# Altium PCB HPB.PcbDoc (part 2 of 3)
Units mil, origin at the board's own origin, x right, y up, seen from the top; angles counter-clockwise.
Board outline 7000 x 12000 mil, 6 copper layers (Top Layer, Int1 (GND), Int2 (Sign), Int3 (Sign), Int4 (PWR), Bottom Layer), stack 61.068 mil thick; 321 components, 232 nets, 1034 pads, 269 vias.
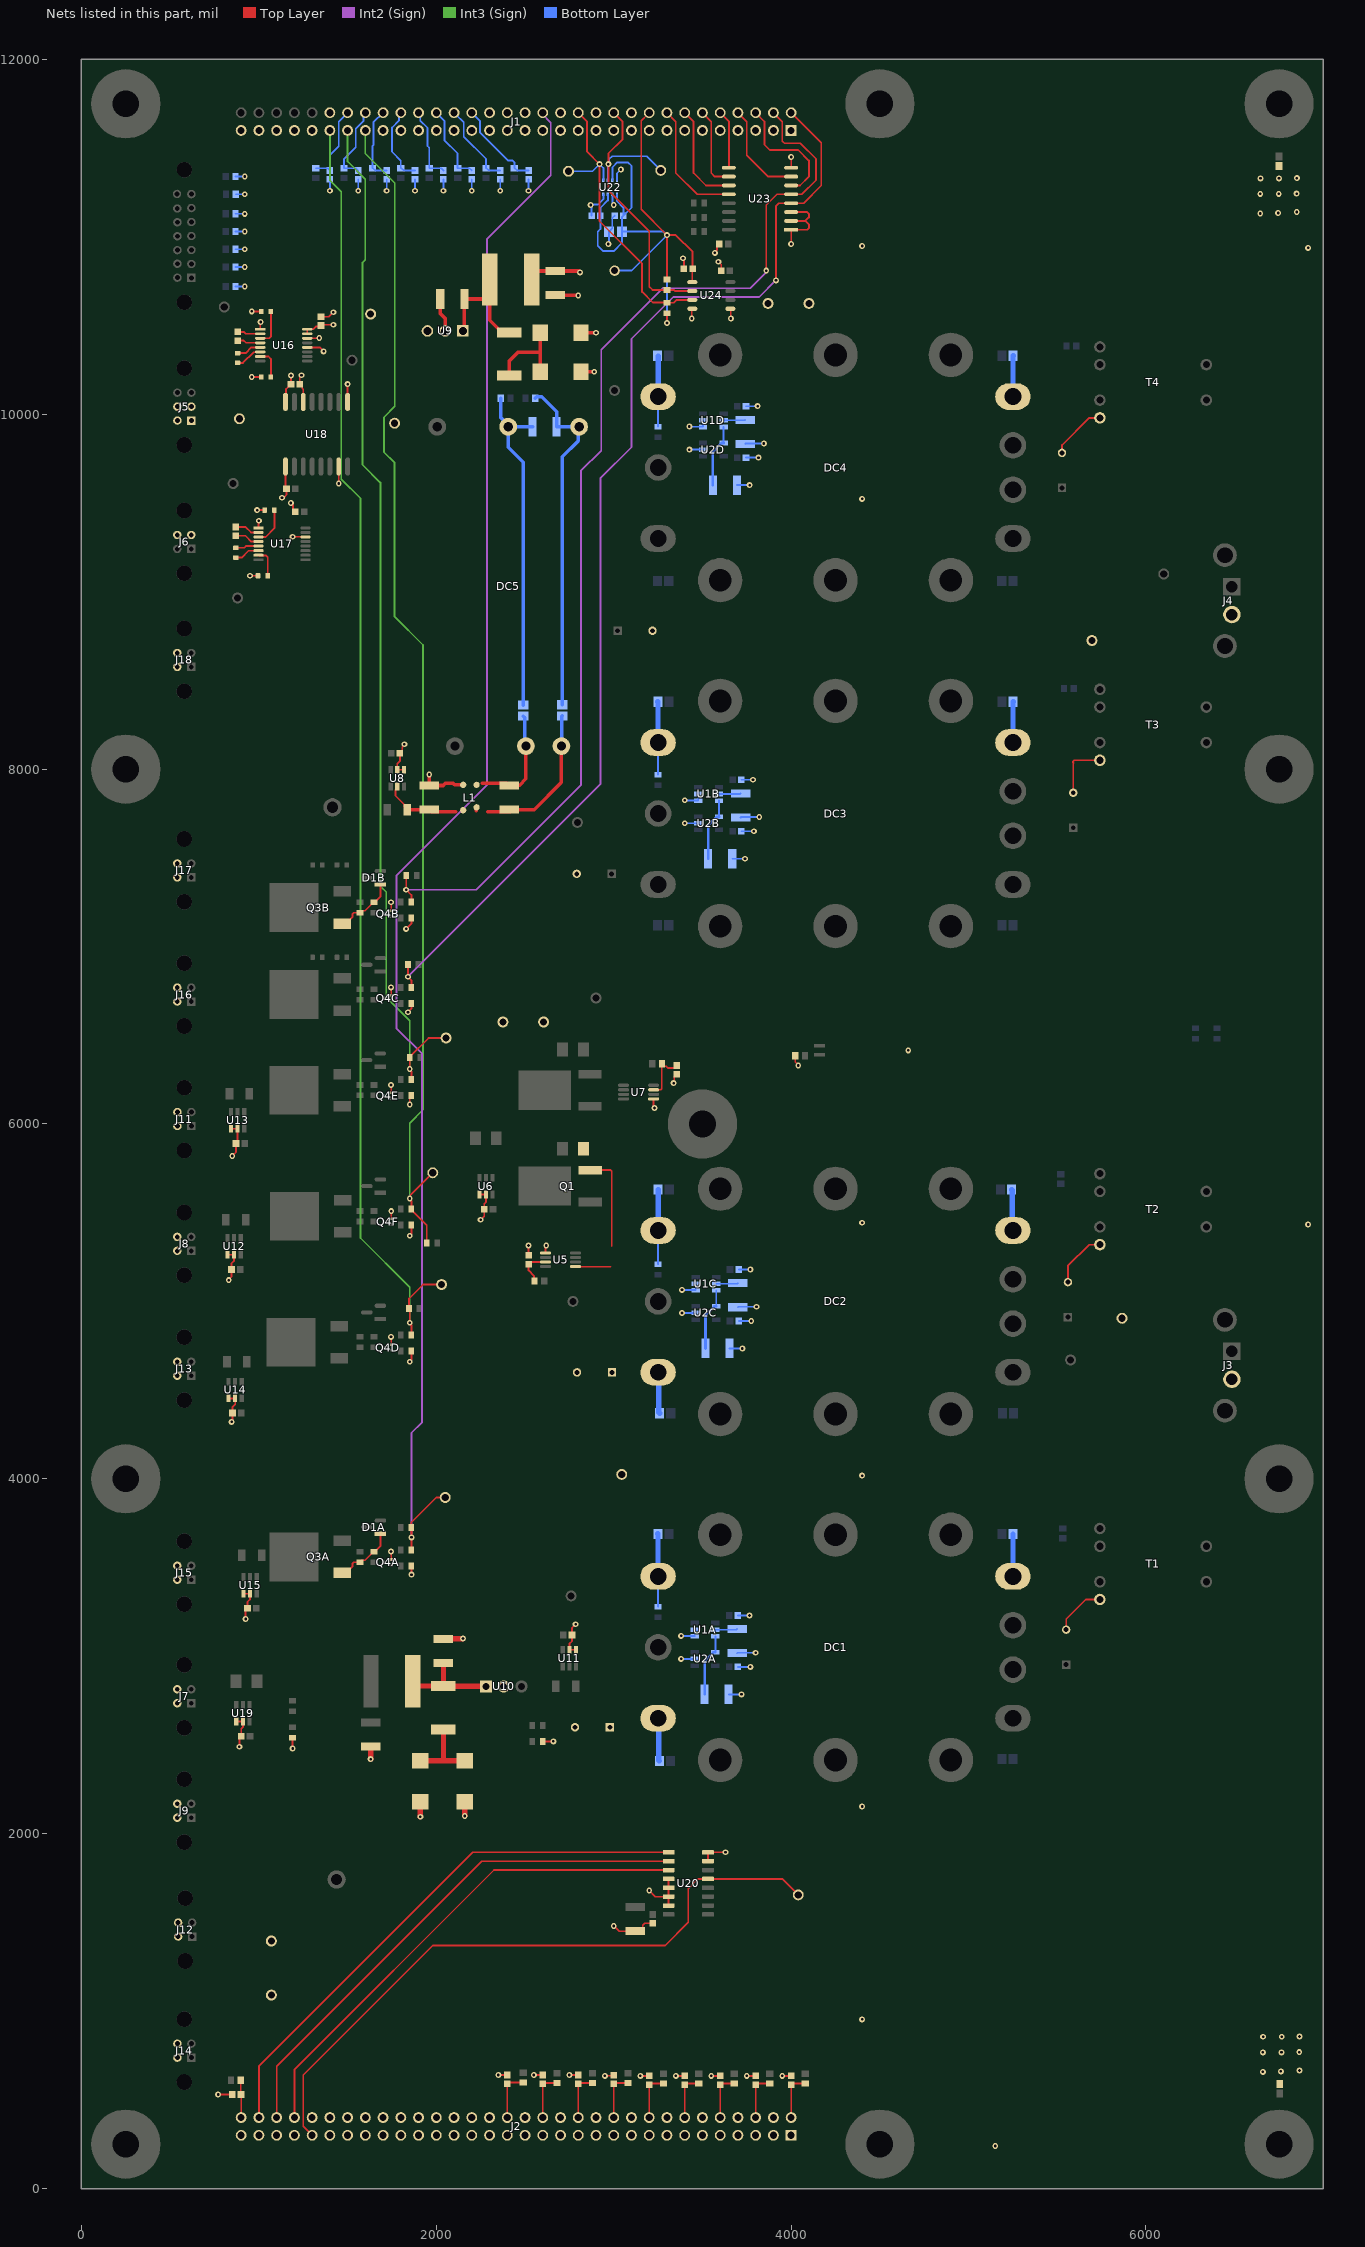
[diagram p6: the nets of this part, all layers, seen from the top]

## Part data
C1 C2 C5 C6 C7 C8 C16 C17 C18 C19 C22 C23 C26 C27 C30 C31 C32 C36: library part CMP-001-00109-9, "0805 Arcshield HV 4.7nF Ceramic Multilayer Cap; 1000VDC; +125C; X7R Dielec; +/-10%", Capacitance=4.7nF, Case Code (Imperial)=0805, Dielectric=X7R, Dielectric Material=Ceramic, Max Operating Temperature=125°C, Min Operating Temperature=-55°C, Tolerance=10%, Voltage Rating=1kV
C3 C4 C14 C15 C20 C21 C28 C29: library part CMP-001-00084-11, "Cap Ceramic 0.22uF 1000V X7R 20% Radial 5mm 125°C Bulk", Capacitance=220nF, Case/Package=Radial, Dielectric=X7R, Manufacturer PN=RDER73A224MUB1H03B, Max Operating Temperature=125°C, Min Operating Temperature=-55°C, Resistor Type=Ceramic, Tolerance=20%, Voltage=1kV
C13 C24 C25 C37 C38 C45 C46 C49 C50 C51 C52 C53 C54 C55 C56 C57 C58 C65 C66 C67 C68 C69 C70 C72 C73 C74 C75 C76 C77 C78 C79 C80 C82 C83 C84 C85 C86 C87 C88 C89 C90A C90B C90C C90D C93A C93B C93C C93D: library part CMP-001-00017-14, "Chip Capacitor, 100 nF, +/- 10%, 50 V, 0603 (1608 Metric)", Capacitance=100nF, Capacitor Type=Ceramic, Case/Package=0603, Max Operating Temperature=125°C, Min Operating Temperature=-55°C, Tolerance=10%, Voltage Rating=50V
C33 C34 C35 C39 C43: library part CMP-001-00184-9, "Chip Capacitor, 10uF, 10%, 50 V, X7R 1210 (3225 Metric)", Capacitance=10uF, Capacitor Type=Ceramic, Case/Package=1210, Dielectric=X7R, Max Operating Temperature=125°C, Min Operating Temperature=-55°C, Tolerance=10%, Voltage Rating=50V
C40 C44: library part CMP-001-00183-9, "Chip Capacitor, 4.7uF, 10%, 50 V, X7R 1210 (3225 Metric)", Capacitance=4.7uF, Capacitor Type=Ceramic, Case/Package=1210, Dielectric=X7R, Max Operating Temperature=125°C, Min Operating Temperature=-55°C, Tolerance=10%, Voltage Rating=50V
C41 C42 C47 C48: library part CMP-001-00088-9, "10uF Solid MnO2 Tantalum Electrolytic Capacitor; 50 V dc +/-10%; T491 Series", Capacitance=10uF, Case Code (Imperial)=2917, Dielectric Material=Tantalum, ESR (Equivalent Series Resistance)=800mR, Leakage Current=5uA, Manufacturer=KEMET, Max Operating Temperature=125°C, Min Operating Temperature=-55°C, Package Quantity=20, Ripple Current=433mA, Tolerance=10%, Voltage=50V
C59 C60 C61 C62 C63 C64: library part CMP-001-00077-11, "Chip Capacitor, 470nF +/-20%, 25V, 0603, Thickness 1 mm", Capacitance=470nF, Capacitor Type=Ceramic, Case/Package=0603, Max Operating Temperature=85°C, Min Operating Temperature=-55°C, Tolerance=10%, Voltage Rating=25V
C71 C91A C91B C91C C91D C92A C92B C92C C92D: library part CMP-001-00181-9, "Chip Capacitor, 1uF, 10%, 50 V, X7R 1210 (3225 Metric)", Capacitance=1uF, Capacitor Type=Ceramic, Case/Package=1210, Dielectric=X7R, Max Operating Temperature=125°C, Min Operating Temperature=-55°C, Tolerance=10%, Voltage Rating=50V
C81: library part CMP-001-00167-10, "Chip Capacitor, 2.2uF, 10%, 50 V, X7R 0805 (2012 Metric)", Capacitance=2.2uF, Capacitor Type=Ceramic, Case/Package=0805, Dielectric=X7R, Max Operating Temperature=125°C, Min Operating Temperature=-55°C, Tolerance=10%, Voltage Rating=50V
D1A D1B D1C D1D D1E D1F: library part CMP-004-00069-1, "Diode Zener Single 10 Volt 5% 250m Watt Automotive 3-Pin SOT-23"
DC1 DC2 DC3 DC4: library part CMP-019-00060-1, "375C Series 150 W Single Output 24 V DC-DC Converter", Isolation Voltage=3kV, Max Input Voltage=425V, Max Operating Temperature=100°C, Max Output Current=6.25A, Max Power Dissipation=150W, Min Input Voltage=250V, Min Operating Temperature=-20°C, Output Voltage=24V
DC5: library part CMP-019-00061-2, "30W DC/DC-Converter 'MEDLINE' 2\"x1\" 5kV reg 4: 1", Current - Output (Max)=1.25A, Operating Temperature="-40°C ~ 105°C (With Derating)", Package / Case="6-DIP Module, 5 Leads", Power (Watts)="30 W", Voltage - Input (Max)=36V, Voltage - Input (Min)=9V, Voltage - Isolation="5 kV", Voltage - Output 1=24V
FB1 FB2: library part CMP-00000-1, "Ferrite Beads Multi-Layer 120Ohm 25% 100MHz 3A 0.025Ohm DCR 0603 T/R", Case Code (Imperial)=0603, Case Code (Metric)=1608, Current Rating=3A, DC Resistance (DCR)=25mR, Frequency=100MHz, Max Operating Temperature=125°C, Min Operating Temperature=-55°C, Package Quantity=1, Tolerance=25%
J1 J2: library part CMP-002-00093-2, "Conn Elevated Socket SKT 64 POS 2.54mm Solder ST Top Entry Thru-Hole Tube", Color=Black, Contact Resistance=10mR, Current Rating=6.9A, Max Operating Temperature=125°C, Max Voltage Rating (AC)=550V, Min Operating Temperature=-55°C, Package Quantity=1
J3 J4: library part CMP-002-00075-3, "Conn Header R/a 2POS 4MM", Color=Black, Contact Resistance=25mR, Current Rating=40A, Insulation Resistance=100MR, Manufacturer=Harwin, Max Operating Temperature=125°C, Maximum Voltage=800V, Min Operating Temperature=-55°C
J5: library part CMP-002-00076-5, "Conn Header R/a 6POS 2MM", Color=Black, Contact Resistance=25mR, Current Rating=3A, Insulation Resistance=100MR, Manufacturer=Harwin, Max Operating Temperature=125°C, Max Voltage Rating (AC)=120V, Maximum Voltage=800V, Min Operating Temperature=-55°C
J6 J7 J8 J9 J11 J12 J13 J14 J15 J16 J17 J18: library part CMP-002-00095-3, "HARWIN - M80-5400442 - Wire-To-Board Connector, 2 mm, 4 Contacts, Header, Datamate J-Tek M80 Series, Through Hole, 2 Rows", Color=Black, Contact Resistance=25mR, Current Rating=2.2A, Insulation Resistance=100MR, Manufacturer=Harwin, Max Operating Temperature=125°C, Maximum Voltage=800V, Min Operating Temperature=-55°C
J10: library part CMP-002-00100-2, "Conn Datamate M 14 POS 2mm Solder RA Thru-Hole Tube", Color=Black, Contact Resistance=25mR, Current Rating=3A, Manufacturer=Harwin, Max Operating Temperature=125°C, Min Operating Temperature=-55°C, Voltage Rating=800V
J19 J20 J21 J22 J23 J24 J25 J26 J27 J28 J29 J30 J31 J32 J33 J34 J35 J36 J37 J38 J39 J40 J41 J42: library part CMP-002-00083-3, "TEST POINT PC MINI .040D WHITE", Color=White
L1: library part CMP-006-00027-1, "Ind Common Mode Choke Wirewound 100 Ohm 100MHz 6A 2020 Embossed T/R", Case/Package=2020, DC Resistance (DCR)=13mR, Max Current Rating=6A, Max Operating Temperature=85°C, Min Operating Temperature=-40°C, Resistor Type=Wirewound, Test Frequency=100MHz, Tolerance=40%, Voltage Rating (DC)=50V
L2 L3: library part CMP-006-00026-2, "WE-LQS Series; Shielded Wire-wound SMD Inductor 12", Case/Package=Nonstandard, Current Rating=2.8A, DC Resistance (DCR)=40mR, Inductance=12uH, Inductance Tolerance=20%, Max Operating Temperature=125°C, Min Operating Temperature=-40°C, Resistor Type=Wirewound, Saturation Current=3.8A, Self Resonant Frequency=21MHz, Test Frequency=100kHz
MH1 MH2 MH3 MH4 MH5 MH6 MH7 MH8 MH9 MH10 MH11: library part CMP-00028-00015-1, "MARS2 Project 6-32 Mounting Hole Plated ."
Q1 Q2: library part CMP-013-00055-1, "Trans MOSFET N-CH 100V 70A Automotive 3-Pin(2+Tab) DPAK T/R", Case/Package=TO-252-3, Continuous Drain Current (ID)=70A, Drain to Source Voltage (Vdss)=100V, Input Capacitance=3.1nF, Max Operating Temperature=175°C, Max Power Dissipation=85W, Min Operating Temperature=-55°C
Q3A Q3B Q3C Q3D Q3E Q3F: library part CMP-013-00042-2, "MOSFET P-CH 100V 13A DPAK", Case/Package=TO-252-3, Continuous Drain Current (ID)=13A, Drain to Source Breakdown Voltage=-100V, Drain to Source Resistance=205mR, Gate to Source Voltage (Vgs)=20V, Input Capacitance=760pF, Max Operating Temperature=150°C, Max Power Dissipation=66W, Min Operating Temperature=-55°C, Threshold Voltage=-4V
Q4A Q4B Q4C Q4D Q4E Q4F: library part CMP-013-00028-3, "NPN General Purpose Transistor, 3-Pin SOT-723, Pb-Free, Tape and Reel", Case/Package=SOT-723
R1 R6 R14 R17: library part CMP-009-01151-1, "Chip Resistor, 75 Ohm, +/- 1%, 0.1 W, -55 to 155 degC, 0603 (1608 Metric)", Case/Package=0603, Max Operating Temperature=155°C, Min Operating Temperature=-55°C, Power=100mW, Tolerance=1%, Voltage Rating=75V
R11 R16 R21 R25: library part CMP-009-01001-3, "Chip Resistor, 49.9k Ohm, +/- 1%, 0.1 W, -55 to 155 degC, 0603 (1608 Metric)", Case/Package=0603, Max Operating Temperature=155°C, Min Operating Temperature=-55°C, Power=100mW, Tolerance=1%, Voltage Rating=75V
R12 R13: library part CMP-009-00006-6, "Chip Resistor, 0 Ohm, 0.1 W, -55 to 155 degC, 0603 (1608 Metric)", Case/Package=0603, Max Operating Temperature=155°C, Min Operating Temperature=-55°C, Power=100mW, Tolerance=5%, Voltage Rating=50V
R15 R18 R19 R49: library part CMP-009-01193-1, "Res Metal Strip 1206 0.01 Ohm 1% 1W ±75ppm/°C Molded SMD SMD Embossed Plastic T/R", Case Code (Imperial)=1206, Manufacturer PN=WSLP1206R0100FEA, Max Operating Temperature=170°C, Max Power Dissipation=1W, Min Operating Temperature=-65°C, Resistance=10mR, Resistance Tolerance=1%, Resistor Type="Metal Strip", Temperature Coefficient=75ppm/°C
R20: library part CMP-009-01006-3, "Chip Resistor, 56.2k Ohm, +/- 1%, 0.1 W, -55 to 155 degC, 0603 (1608 Metric)", Case/Package=0603, Max Operating Temperature=155°C, Min Operating Temperature=-55°C, Power=100mW, Tolerance=1%, Voltage Rating=75V
R22 R23 R28 R34 R35 R38 R40 R42 R46 R50 R51 R52 R53 R54 R55 R61 R62 R63: library part CMP-009-01135-1, "Chip Resistor, 51.1 Ohm, +/- 1%, 0.1 W, -55 to 155 degC, 0603 (1608 Metric)", Case/Package=0603, Max Operating Temperature=155°C, Min Operating Temperature=-55°C, Power=100mW, Tolerance=1%, Voltage Rating=75V
R24 R33 R70A R70B R70C R70D R70E R70F R71A R71B R71C R71D R71E R71F R77A R77B R77C R77D R77E R77F R78A R78B R78C R78D R78E R78F: library part CMP-009-00017-7, "Chip Resistor, 10 KOhm, +/- 1%, 01 W, -55 to 155 degC, 0603 (1608 Metric)", Case/Package=0603, Max Operating Temperature=155°C, Min Operating Temperature=-55°C, Power=100mW, Tolerance=1%, Voltage Rating=50V
R26 R31 R37 R39 R41 R45: library part CMP-009-01194-1, "Res Thick Film 1206 0.033 Ohm 1% 1W ±75ppm/C Pad SMD Automotive T/R", Case Code (Imperial)=1206, Manufacturer PN=ERJ-8CWFR033V, Max Operating Temperature=125°C, Max Power Dissipation=1W, Min Operating Temperature=-55°C, Ratings=AEC-Q200, Resistance=33mR, Resistance Tolerance=1%, Temperature Coefficient=75ppm/°C
R27: library part CMP-009-01065-1, "Chip Resistor, 100k Ohm, +/- 1%, 0.1 W, -55 to 155 degC, 0603 (1608 Metric)", Case/Package=0603, Max Operating Temperature=155°C, Min Operating Temperature=-55°C, Power=100mW, Tolerance=1%, Voltage Rating=75V
R29: library part CMP-009-01062-1, "Chip Resistor, 931k Ohm, +/- 1%, 0.1 W, -55 to 155 degC, 0603 (1608 Metric)", Case/Package=0603, Max Operating Temperature=155°C, Min Operating Temperature=-55°C, Power=100mW, Tolerance=1%, Voltage Rating=75V
R30 R32: library part CMP-009-01195-2, "Res Thick Film 2512 1 Ohm 1% 1W ±100ppm/°C Molded SMD SMD", Case Code (Imperial)=2512, Manufacture PN=CRCW25121R00FKEG, Max Operating Temperature=155°C, Max Power Dissipation=1W, Min Operating Temperature=-55°C, Ratings=AEC-Q200, Resistance=1R, Resistance Tolerance=1%, Resistor Type="Thick Film", Temperature Coefficient=100ppm/°C, Voltage Rating=500V
R36 R69A R69B R69C R69D R69E R69F: library part CMP-009-00023-6, "Chip Resistor, 100 KOhm, +/- 1%, 0.1 W, -55 to 155 degC, 0603 (1608 Metric)", Case/Package=0603, Max Operating Temperature=155°C, Min Operating Temperature=-55°C, Power=100mW, Tolerance=1%, Voltage Rating=50V
R43 R44 R47 R48: library part CMP-009-00175-3, Case/Package=0603, Max Operating Temperature=155°C, Min Operating Temperature=-55°C
R56 R57 R58 R59 R60 R64 R65 R66: library part CMP-009-00865-4, "Chip Resistor, 7.15k Ohm, +/- 1%, 0.1 W, -55 to 155 degC, 0603 (1608 Metric)", Case/Package=0603, Max Operating Temperature=155°C, Min Operating Temperature=-55°C, Power=100mW, Tolerance=1%, Voltage Rating=75V
R67 R68 R72 R73 R74: library part CMP-009-00031-7, "Chip Resistor, 4.7 KOhm, +/- 1%, 0.1 W, -55 to 155 degC, 0603 (1608 Metric)", Case/Package=0603, Max Operating Temperature=155°C, Min Operating Temperature=-55°C, Power=100mW, Tolerance=1%
R75 R76: library part CMP-009-01066-2, "Chip Resistor, 100 Ohm, +/- 1%, 0.1 W, -55 to 155 degC, 0603 (1608 Metric)", Case/Package=0603, Max Operating Temperature=155°C, Min Operating Temperature=-55°C, Power=100mW, Tolerance=1%, Voltage Rating=75V
SY: library part CMP-00028-00011-3, "Layer Indicator for 6 layer board"
T1 T2 T3 T4: library part CMP-012-00000-1, "3 W 101 to 187 uH 40 to 50 mOhm DCR PR Bus Toroidal Inductor", Manufacturer=Vicor
TP1 TP2: library part CMP-001-0000-5, "PC TEST POINT COMPACT RED", Color=Red
TP3: library part CMP-002-00037-2, "Test Point, Orange, Height 4.6 mm, Tail Length 3 mm, 1-Pin THD, RoHS", Colour=Orange, Manufacturer=Keystone, Package Description="1-Pin Through Hole Device, Dia 2.54 mm", Package Quantity=10
TP4 TP5 TP6 TP7 TP8 TP9: library part CMP-001-0002-3, "TEST POINT PC MINI .040D BLACK", Color=Black
U1A U1B U1C U1D: library part CMP-019-00086-3, "650-nA quiescent current, 12-ppm/°C drift, ultra-low-power precision voltage reference, 1.024V, 6-SOT-23 -40 to 125"
U2A U2B U2C U2D: library part CMP-014-00029-3, "Automotive, 2.5-ns, high-speed, rail-to-rail comparator with push-pull outputs 5-SOT-23 -40 to 125"
U5 U7: library part CMP-004-00036-2, "OR Controller N+1 ORing Controller N-Channel N:1 8-MSOP", Case/Package=MSOP, Max Operating Temperature=125°C, Max Output Current=210uA, Max Supply Voltage=80V, Min Operating Temperature=-40°C, Min Supply Voltage=9V
U6 U19: library part CMP-014-00007-3, "MAX4173 Series 28 V 1.4 MHz Voltage Current Sense Operational Amplifier - SOT-23", Input Bias Current=700uA, Input Offset Voltage (Vos)=300uV, Max Operating Temperature=85°C, Max Supply Current=1mA, Max Supply Voltage=28V, Min Operating Temperature=-40°C, Min Supply Voltage=3V, Nominal Supply Current=420uA
U8 U11 U12 U13 U14 U15: library part CMP-014-00008-1, "MAX4173 Series 28 V 1.2 MHz Voltage Current Sense Operational Amplifier - SOT-23", Input Bias Current=700uA, Max Operating Temperature=85°C, Max Supply Voltage=28V, Min Operating Temperature=-40°C, Min Supply Voltage=3V, Operating Supply Current=420uA
U9: library part CMP-019-00059-1, "0.5A DC/DC-Converter 'INNOLINE' SIP3 reg; V. In: 7-28; V. Out: 5.0; mA. Out: 500", Case/Package=SIP, Current - Output 1=500mA, Max Input Voltage=28V, Max Operating Temperature=85°C, Max Output Power=2.5W, Max Output Voltage=5V, Max Power Dissipation=3W, Min Input Voltage=7V, Min Operating Temperature=-40°C
U10: library part CMP-019-00062-2, "0.5A DC/DC-Converter 'INNOLINE' SIP3 reg; V. In: 6.5-32; V. Out: 5.0; mA. Out: 500", Case/Package=SIP, Current - Output 1=500mA, Isolation Voltage=2kV, Max Input Voltage=32V, Max Operating Temperature=85°C, Max Output Power=2.5W, Max Output Voltage=5V, Max Power Dissipation=3W, Min Input Voltage=6.5V, Min Operating Temperature=-40°C, Nominal Input Voltage=24V, Switching Frequency=380kHz
U16 U17: library part CMP-015-00011-1, "MAX3221 Series 235 kbps 5.5 V Surface Mount RS-232 Transceiver - SSOP-16"
U18: library part CMP-015-00014-3, "5000Vrms 25kV/us 1Mbps Digital Isolation RS232,TTL RS485", Case/Package=SOIC, Isolated Power=No, Max Input Current=10uA, Max Operating Temperature=105°C, Max Supply Voltage=5.5V, Min Operating Temperature=-40°C, Min Supply Voltage=3V, Nominal Supply Current=800uA
U20: library part CMP-016-00018-2, "Automotive 5-V, 8: 1 1-channel general-purpose multiplexer 16-SOIC -40 to 125", Case/Package=SOIC, High Level Output Current=7.8mA, Max Operating Temperature=125°C, Max Supply Voltage=6V, Min Operating Temperature=-40°C, Min Supply Voltage=2V
U21: library part CMP-010-00024-2, "SENSOR ANALOG -55C-150C 2FLATPK / Two-Twrminal IC Temperature Transducer", Case/Package=Ceramic, Forward Voltage=44V, Max Operating Temperature=150°C, Max Supply Voltage=30V, Min Operating Temperature=-55°C, Min Supply Voltage=4V, Output Current=298.2uA
U22: library part CMP-010-00027-1, "SENSOR PRESSURE HUMIDITY TEMP", Max Operating Temperature=85°C, Min Operating Temperature=-40°C
U23: library part CMP-015-00015-1, "8-bit 1.65- to 5.5-V I2C/SMBus I/O expander with interrupt, & config registers 16-SOIC -40 to 85", Case/Package=SOIC, Frequency=400kHz, Max Operating Temperature=85°C, Min Operating Temperature=-40°C
U24: library part CMP-024-00005-1, "I²C Digital Isolator 2500Vrms 2 Channel 1Mbps 25kV/µs CMTI 8-SOIC (0.154, 3.90mm Width)", Max Operating Temperature=105°C, Max Supply Voltage=5.5V, Min Operating Temperature=-40°C, Min Supply Voltage=3V, Nominal Supply Current=5mA, Operating Supply Voltage=5V

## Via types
v1: diameter 33, hole 15, Top Layer to Bottom Layer, 269 vias

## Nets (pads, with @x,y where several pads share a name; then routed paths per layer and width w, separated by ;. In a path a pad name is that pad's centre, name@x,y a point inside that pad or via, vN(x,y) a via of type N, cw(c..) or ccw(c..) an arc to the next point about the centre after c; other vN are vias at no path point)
24V_UNSWCH_BUS_CURRENT: C69.2 J2.18 R50.2 | length 268.3
  Top Layer w10: J2.18@3200,400 C69.2@3200,585.39 3207.05,592.44 R50.2@3280,592.44
BAYCAT_3V3: C81.2 C82.2 C83.2 C84.2 J1.18 R67.2 R68.2 TP3.1 U22.2 U22.6 U22.8 U24.1 | length 3841.2
  Top Layer w10: J1.18@3200,11700 3200,11690 3190,11690 3154.49,11654.49 3154.49,11155.51 v1(3300,11010) ; v1(3300,10515) R67.2@3300,10570.47 ; R68.2@3300,10760 v1(3300,11010) ; U24.1@3442.72,10745 3442.72,10818.11 C84.2@3444.61,10820 3444.61,10915.39 3350,11010 v1(3300,11010)
  Bottom Layer w10: U22.6@2967.2,11239.65 2967.2,11205.55 2924.61,11162.95 C82.2@2924.61,11120 2924.61,11044.61 2910,11030 2910,10950 2940,10920 3000,10920 3046.42,10966.42 C81.2@3046.42,11030 ; U22.2@2992.8,11320.35 2992.8,11392.8 3020,11420 3080,11420 3100,11400 3100,11165.39 C83.2@3054.61,11120 ; TP3.1@3005,10810 3100,10810 v1(3300,11010) ; U22.8@3018.39,11239.65 3018.39,11201.61 3054.61,11165.39 C83.2@3054.61,11120 ; v1(3300,10515) v1(3300,11010) ; C81.2@3046.42,11030 3280,11030 v1(3300,11010) ; C81.2@3046.42,11030 3046.42,11111.81 C83.2@3054.61,11120
CHASIS1: FB1.1
  other v1: 4400,9523.34 6914.03,10938.34 4400,10948.34 6643.58,11132.33 6745,11135 6850,11140 6643.58,11242.33 6748.58,11242.33 6848.9,11243.8 6645,11330 6750,11330 6850.32,11331.47
CHASIS2: FB2.1
  other v1: 5150,240 6658.58,657.33 6760,660 6865,665 6658.58,767.33 6763.58,767.33 6863.9,768.8 6660,855 6765,855 6865.32,856.47 4400,953.34 4400,2153.34 4400,4018.34 6914.03,5433.34 4400,5443.34 4660,6415
DIO_SPARE_0: J1.2 R70C.1 R77C.1 U23.4 | length 6409.9
  Top Layer w10: R77C.1@1840.47,6900 1840,6899.53 v1(1840,6830) 1859.53,6810.47 R70C.1@1859.53,6770 ; v1(3915,10755) 3915,11175 3930,11190 U23.4@4000,11190 4070,11190 4170,11290 4170,11530 J1.2@4000,11700
  Int2 (Sign) w10: v1(1840,6830) 2925,7915 2925,9640 3100,9815 3100,10425 3336.11,10661.11 3819.56,10661.11 3913.45,10755 v1(3915,10755)
DIO_SPARE_1: J1.4 R70B.1 R77B.1 U23.5 | length 6258.4
  Top Layer w10: R77B.1@1830.94,7400 1830,7399.06 v1(1830,7320) 1859.53,7290.47 R70B.1@1859.53,7250 ; v1(3860,10810) 3860,11180 3920,11240 U23.5@4000,11240 4060,11240 4140,11320 4140,11440 4052.18,11527.82 3962.18,11527.82 3950,11540 3950,11650 J1.4@3900,11700
  Int2 (Sign) w10: v1(1830,7320) 2225,7320 2815,7910 2815,9680 2814.14,9680.86 2929.09,9795.81 2929.09,10364.09 3278.36,10713.36 3286.64,10713.36 3290,10710 3770,10710 3857.13,10797.13 3857.13,10807.13 v1(3860,10810)
DIO_SPARE_2: J1.6 U23.6 | length 698.7
  Top Layer w10: J1.6@3800,11700 3850,11650 3850,11520 3880,11490 4040,11490 4100,11430 4100,11340 4050,11290 U23.6@4000,11290
DIO_SPARE_3: J1.8 U23.7 | length 560.4
  Top Layer w10: J1.8@3700,11700 3750,11650 3750,11460 3870,11340 U23.7@4000,11340
DIO_SPARE_4: J1.10 U23.9 | length 331.4
  Top Layer w10: J1.10@3600,11700 3650,11650 3650,11391.61 U23.9@3648.39,11390
DIO_SPARE_5: J1.12 U23.10 | length 467.4
  Top Layer w10: J1.12@3500,11700 3550,11650 3550,11360 3570,11340 U23.10@3648.39,11340
DIO_SPARE_6: J1.14 U23.11 | length 588.1
  Top Layer w10: J1.14@3400,11700 3450,11650 3450,11360 3520,11290 U23.11@3648.39,11290
DIO_SPARE_7: J1.16 U23.12 | length 708.8
  Top Layer w10: J1.16@3300,11700 3350,11650 3350,11360 3470,11240 U23.12@3648.39,11240
FAULT_MUX_A: J2.58 U20.11 | length 2844.8
  Top Layer w10: J2.58@1200,400 1200,670 2325,1795 U20.11@3308.78,1795
FAULT_MUX_B: J2.60 U20.10 | length 2977.2
  Top Layer w10: J2.60@1100,400 1100,690 2255,1845 U20.10@3308.78,1845
FAULT_MUX_C: J2.62 U20.9 | length 3097.9
  Top Layer w10: J2.62@1000,400 1000,690 2205,1895 U20.9@3308.78,1895
FAULT_SENSE_HCB: J2.55 J40.1 U20.5 | length 3757
  Top Layer w10: J2.55@1300,300 1250,350 1250,640 1980,1370 3290,1370 3420,1500 3420,1690 3475,1745 3950,1745 J40.1@4040,1655
FAULT_SENSE_IPB1: J2.51
FAULT_SENSE_IPB2: J2.53
GF_AMP_TEMP_F: J2.59
GF_ANNODE_SEL_EN: J2.9
GF_CHASSIS_SEL_EN: J2.11
GF_SIG: J2.47
GF_SOURCE_SEL_A: J2.1
GF_SOURCE_SEL_B: J2.3
GF_SOURCE_SEL_C: J2.5
GF_SOURCE_SEL_ENn: J2.7
GNDA: C4.2 C6.2 C13.1 C15.2 C17.2 C21.2 C23.2 C24.1 C25.1 C29.2 C31.2 C34.1 C37.1 C38.1 C43.1 C44.1 C45.1 C46.1 C47.2 C48.2 C49.1 C50.1 C51.1 C52.1 C53.1 C54.1 C55.1 C56.1 C62.1 C63.1 C65.1 C66.1 C69.1 C70.1 C71.1 C72.1 C73.1 C74.1 C75.1 C76.1 C77.1 C78.1 C79.1 C80.1 C81.1 C82.1 C83.1 C84.1 C85.1 C86.1 C87.1 C88.1 C89.1 C90A.1 C90B.1 C90C.1 C90D.1 C91A.1 C91B.1 C91C.1 C91D.1 C92A.1 C92B.1 C92C.1 C92D.1 C93A.1 C93B.1 C93C.1 C93D.1 DC1.5 DC2.5 DC3.5 DC4.5 J1.20 J1.24 J1.28 J1.32 J1.54 J1.55 J1.57 J1.59 J1.61 J1.63 J2.4 J2.8 J2.12 J2.13 J2.16 J2.17 J2.20 J2.21 J2.24 J2.25 J2.28 J2.29 J2.32 J2.33 J2.37 J2.40 J2.41 J2.44 J2.45 J2.48 J2.49 J2.52 J2.56 J6.2 J6.4 J7.3 J7.4 J8.3 J8.4 J9.3 J9.4 J11.3 J11.4 J12.3 J12.4 J13.3 J13.4 J14.3 J14.4 J15.3 J15.4 J16.3 J16.4 J17.3 J17.4 J18.3 J18.4 L1.2 Q4A.2 Q4B.2 Q4C.2 Q4D.2 Q4E.2 Q4F.2 R11.2 R16.2 R21.2 R24.1 R25.2 R36.1 R56.1 R57.1 R58.1 R59.1 R60.1 R64.1 R65.1 R66.1 R71A.1 R71B.1 R71C.1 R71D.1 R71E.1 R71F.1 TP4.1 TP5.1 TP6.1 TP7.1 TP8.1 TP9.1 U1A.1 U1A.2 U1B.1 U1B.2 U1C.1 U1C.2 U1D.1 U1D.2 U2A.2 U2B.2 U2C.2 U2D.2 U5.5 U6.1 U6.2 U7.5 U8.1 U8.2 U10.2 U11.1 U11.2 U12.1 U12.2 U13.1 U13.2 U14.1 U14.2 U15.1 U15.2 U17.1 U17.14 U18.1 U18.7 U19.1 U19.2 U20.7 U20.8 U20.12 U20.13 U20.14 U20.15 U22.1 U22.5 U22.7 U23.1 U23.2 U23.3 U23.8 U24.4 U24.5 | length 10776.6
  Top Layer w10: v1(770,530) C56.1@850,530 ; U12.1@822.6,5262.76 U12.2@860,5262.76 860,5230 845.39,5215.39 C53.1@845.39,5180 845.39,5139.45 830,5124.06 v1(830,5120) ; U14.1@828.7,4453.58 U14.2@866.1,4453.58 866.1,4420.83 851.5,4406.22 C52.1@851.5,4370.83 851.5,4326.22 v1(846.1,4320.83) ; U13.1@842.6,5972.76 U13.2@880,5972.76 880,5899.21 C54.1@870.79,5890 870.79,5840.79 v1(850,5820) ; U19.1@872.6,2632.76 U19.2@910,2632.76 910,2600 900.79,2590.79 C70.1@900.79,2550 C70.1@890,2560.79 ; v1(890,2490) C70.1@890,2550 ; U15.1@919.41,3352.76 U15.2@950,3352.76 950,3320.46 935.39,3305.86 C87.1@935.39,3270 925,3259.61 v1(925,3210) ; v1(950,9090) C63.1@994.88,9090 ; v1(990,9460) C62.1@1032.44,9460 ; U17.1@997.57,9359.57 997.57,9397.57 v1(1000,9400) ; v1(1130,9530) 1132.87,9532.87 1141.96,9532.87 1155.39,9546.3 C66.1@1155.39,9580 1150,9585.39 U18.1@1150,9705.83 ; v1(1180,9500) 1191.69,9488.31 1191.69,9463.7 C65.1@1205.39,9450 ; v1(1190,2480) R24.1@1190,2540.47 ; v1(1190,9310.3) 1190.95,9309.34 1261.48,9309.34 U17.14@1262.43,9308.39 ; v1(1450,9610) U18.7@1450,9705.83 ; v1(1745,3590) 1746.32,3588.68 1746.32,3547.07 Q4A.2@1747.64,3545.75 ; v1@1745,4800.47 1746.32,4799.15 1746.32,4757.54 Q4D.2@1747.64,4756.22 ; v1@1745,6220.47 1746.32,6219.15 1746.32,6177.54 Q4E.2@1747.64,6176.22 ; v1@1745,6760 1746.32,6758.68 Q4C.2@1746.32,6725.75 ; v1(1745,7250) 1746.32,7248.68 1746.32,7202.81 Q4B.2@1747.64,7201.5 ; v1(1746.32,5508.68) 1746.32,5467.07 Q4F.2@1747.64,5465.75 ; U8.1@1817.4,7997.24 U8.2@1780,7997.24 1780,8030 1794.61,8044.61 C38.1@1794.61,8090 1808.31,8103.7 1808.31,8124.25 1820,8135.94 v1(1820,8140) ; v1(1830,7100) 1859.53,7129.53 R71B.1@1859.53,7160 R71B.1@1859.53,7170.47 ; v1(1840,6630) 1859.53,6649.53 R71C.1@1859.53,6680 ; v1(1850,6110) 1850,6150.47 R71E.1@1859.53,6160 ; R71A.1@1859.53,3510 1859.53,3460.47 v1(1860,3460) ; R71D.1@1859.53,4720.47 R71D.1@1859.53,4720 1859.53,4670.94 v1@1860,4670.47 ; R71F.1@1859.53,5430 1859.53,5380.47 v1@1860,5380 ; U6.1@2242.6,5602.76 U6.2@2280,5602.76 2280,5560 2270,5550 C13.1@2270,5520 2270,5480 v1(2250,5460) ; v1(2350,640) 2350.39,639.61 C45.1@2400,639.61 ; C88.1@2520,5259.61 v1(2520,5315) ; v1(2550,640) 2550.39,639.61 C46.1@2600,639.61 ; R36.1@2599.53,2520 v1(2660,2520) ; U5.5@2615.35,5273.39 2615.35,5310.35 v1(2620,5315) ; v1(2750,640) C24.1@2800,640 ; v1(2785,3180) 2764.61,3159.61 C49.1@2764.61,3120 2764.61,3084.61 2750,3070 U11.2@2750,3037.24 U11.1@2787.4,3037.24 ; v1(2950,635) 2995.79,635 C25.1@3000,639.21 ; v1(3000,1480) 3030,1450 3144.14,1450 3163.87,1469.72 3163.87,1483.87 3175.39,1495.39 C72.1@3220,1495.39 ; v1(3150,635) 3150.39,634.61 C69.1@3200,634.61 ; v1(3200,1680) 3235,1645 U20.14@3308.78,1645 ; U7.5@3224.65,6141.61 3224.65,6095.35 v1(3230,6090) ; U20.15@3308.78,1595 U20.14@3308.78,1645 ; U20.12@3308.78,1745 U20.13@3308.78,1695 U20.14@3308.78,1645 ; v1(3337.5,6230.39) 3337.5,6234.45 3341.3,6238.25 3341.3,6266.69 C89.1@3355,6280.39 ; v1(3350,635) 3350.39,634.61 C37.1@3400,634.61 ; v1(3390,10880) 3390,10875.94 3395.39,10870.55 C84.1@3395.39,10820 ; v1(3440,10540) 3440,10592.28 U24.4@3442.72,10595 ; U20.7@3531.22,1845 U20.8@3531.22,1895 v1(3630,1895) ; v1(3550,635) 3550.39,634.61 C55.1@3600,634.61 ; v1(3570,10910) 3570,10914.06 3581.69,10925.75 3581.69,10946.3 C86.1@3595.39,10960 ; v1(3590,10860) 3605.39,10844.61 C85.1@3605.39,10810 ; U24.5@3657.28,10595 3660,10592.28 v1(3660,10540) ; v1(3750,635) 3750.39,634.61 C51.1@3800,634.61 ; v1(3950,635) 3950.39,634.61 C50.1@4000,634.61 ; v1(4000,10960) U23.1@4000,11040 4090,11040 4100.86,11050.86 4100.86,11069.14 4080,11090 ; U23.2@4000,11090 4080,11090 ; U23.3@4000,11140 4090,11140 4100,11130 4100,11110 4080,11090 ; U23.8@4000,11390 v1(4000,11450) ; R60.1@4022.44,6385 4022.44,6349.33 4040,6331.77 v1(4040,6330)
  Top Layer w20: v1(1960,7970) C34.1@1960,7907.91 2037.91,7907.91 2050,7920 2094.42,7920 2102.81,7911.6 L1.2@2151.37,7911.6
  Top Layer w30: v1(1630,2420) C43.1@1630,2492.09 ; v1(1910,2095) C48.2@1910,2179.84 ; C44.1@2040,3097.91 2147.91,3097.91 v1(2150,3100) ; v1(2160,2100) C47.2@2160,2179.84
  Bottom Layer w10: R66.1@867.56,10720 v1(920,10720) ; R65.1@867.56,10830 v1(920,10830) ; R64.1@867.56,10930 v1(920,10930) ; R59.1@867.56,11030 v1(920,11030) ; R58.1@867.56,11130 v1(920,11130) ; R56.1@867.56,11340 v1(920,11340) ; R57.1@870,11240 v1(920,11240) ; v1(1400,11260) C73.1@1400,11325.39 ; v1(1560,11260) C74.1@1560,11325.39 ; v1(1720,11260) C75.1@1720,11325.39 ; v1(1880,11260) C76.1@1880,11325.39 ; v1(2040,11260) C77.1@2040,11325.39 ; v1(2200,11260) C78.1@2200,11325.39 ; v1(2360,11260) C79.1@2360,11325.39 ; v1(2520,11260) C80.1@2520,11325.39 ; C82.1@2875.39,11120 2875.39,11174.61 v1(2870,11180) 2872.87,11182.87 2912.87,11182.87 2941.61,11211.61 U22.5@2941.61,11239.65 ; v1(2970,10960) 2973.58,10963.58 C81.1@2973.58,11030 2991.69,11048.11 2991.69,11106.3 C83.1@3005.39,11120 ; U22.7@2992.8,11239.65 2992.8,11187.2 v1(3000,11180) 3000,11175.94 v1@3005.39,11170.55 ; U22.1@3018.39,11320.35 3018.39,11358.39 v1(3040,11380) ; C31.2@3247.01,10330 C31.2@3250,10327.01 ; R11.2@3250,3279.53 DC1.5@3250,3450 ; R16.2@3250,5209.53 DC2.5@3250,5400 ; R21.2@3250,7969.53 DC3.5@3250,8150 ; R25.2@3250,9929.53 DC4.5@3250,10100 ; v1(3380,2985) U2A.2@3456.93,2985 ; v1(3380,3115) 3381.2,3113.8 3455.73,3113.8 3456.93,3115 U1A.2@3456.93,3150 ; v1(3385,4935) U2C.2@3461.93,4935 ; v1(3385,5065) 3386.2,5063.8 3460.73,5063.8 3461.93,5065 U1C.2@3461.93,5100 ; v1(3400,7695) U2B.2@3476.93,7695 ; v1(3400,7825) 3401.2,7823.8 3475.73,7823.8 3476.93,7825 U1B.2@3476.93,7860 ; v1(3426.16,9801) U2D.2@3503.09,9801 ; v1(3426.16,9931) 3427.36,9929.8 3501.88,9929.8 3503.09,9931 U1D.2@3503.09,9966 ; C92A.1@3647.91,2785 v1(3720,2785) ; C92C.1@3652.91,4735 v1(3725,4735) ; C92B.1@3667.91,7495 v1(3740,7495) ; C92D.1@3694.07,9601 v1(3766.16,9601) ; C91A.1@3695,3017.09 3697.91,3020 v1(3800,3020) ; C93A.1@3699.61,2940 v1(3770,2940) ; C90A.1@3699.61,3230 v1(3765,3230) ; C91C.1@3700,4967.09 3702.91,4970 v1(3805,4970) ; C93C.1@3704.61,4890 v1(3775,4890) ; C90C.1@3704.61,5180 v1(3770,5180) ; C91B.1@3715,7727.09 3717.91,7730 v1(3820,7730) ; C93B.1@3719.61,7650 v1(3790,7650) ; C90B.1@3719.61,7940 v1(3785,7940) ; C91D.1@3741.16,9833.09 3744.07,9836 v1(3846.16,9836) ; C93D.1@3745.76,9756 v1(3816.16,9756) ; C90D.1@3745.76,10046 v1(3811.16,10046)
  Bottom Layer w30: C6.2@3248.5,3690 3249.25,3689.25 3249.25,3459.53 3250,3458.78 DC1.5@3250,3450 ; C23.2@3248.5,8380 3249.25,8379.25 3249.25,8150.75 DC3.5@3250,8150 ; DC2.5@3250,5400 C17.2@3250,5630 ; DC4.5@3250,10100 C31.2@3250,10327.01
  other v1: 1850,4660 1745,4800 1850,5370 1745,6220 1745,6770
HCB_MEDIA_EN: J1.30 J35.1 R70A.1 R77A.1 | length 8888.6
  Top Layer w10: R77A.1@1859.06,3725 1859.06,3754.06 2000,3895 J35.1@2050,3895 ; R70A.1@1859.53,3600 1859.53,3669.53 v1(1860,3670) 1860,3705 R77A.1@1867.56,3712.56
  Int2 (Sign) w10: v1(1860,3670) 1860,4259.53 1920,4319.53 1920,6395 1775,6540 1775,7400 2285,7910 2285,10986.11 2645.51,11346.62 2645.51,11644.49 2600,11690 J1.30@2600,11700
HPB_5V_CURRENT: C45.2 J2.34 R34.2 | length 283.3
  Top Layer w10: J2.34@2400,400 C45.2@2400,590.39 2407.05,597.44 R34.2@2490,597.44
HPB_5V_VOLTAGE: C46.2 J2.30 R35.2 | length 272.3
  Top Layer w10: J2.30@2600,400 C46.2@2600,590.39 2604.61,595 R35.2@2680,595
HPB_24V_CURRENT: C24.2 J2.26 R22.2 | length 272.3
  Top Layer w10: J2.26@2800,400 C24.2@2800,590.79 2803.65,594.44 R22.2@2880,594.44
HPB_24V_VOLTAGE: C25.2 J2.22 R23.2 | length 272
  Top Layer w10: J2.22@3000,400 C25.2@3000,590 3004.88,594.88 R23.2@3080,594.88
HPB_CISCO1_CURRENT: C50.2 J2.2 R38.2 | length 268.3
  Top Layer w10: J2.2@4000,400 C50.2@4000,585.39 4007.05,592.44 R38.2@4080,592.44
HPB_CISCO1_EN: J1.49 J32.1 R70F.1 R77F.1 | length 6724.5
  Top Layer w10: R77F.1@1945.47,5330 1945.47,5430.12 1859.53,5516.06 R70F.1@1859.53,5520 1859.53,5566.41 1850,5575.94 v1(1850,5580) 1852.87,5582.87 1852.87,5597.87 J32.1@1980,5725
  Int3 (Sign) w10: J1.49@1600,11600 1600,11470 1765.91,11304.09 1765.91,10044.53 1705,9983.63 1705,9787.33 1765,9727.33 1765,8860 1925,8700 1925,6080 1850,6005 v1(1850,5580)
HPB_CISCO2_CURRENT: C51.2 J2.6 R40.2 | length 268.3
  Top Layer w10: J2.6@3800,400 C51.2@3800,585.39 3807.05,592.44 R40.2@3880,592.44
HPB_CISCO2_EN: J1.51 J33.1 R70E.1 R77E.1 | length 5829.7
  Top Layer w10: R70E.1@1859.53,6250 1859.53,6296.41 1850,6305.94 v1(1850,6310) 1850,6374.53 R77E.1@1850.47,6375 1850.47,6378.94 1956.54,6485 J33.1@2055,6485
  Int3 (Sign) w10: J1.51@1500,11600 1500,11425 1600,11325 1600,10870.87 1584.09,10854.96 1584.09,9715.91 1685,9615 1685,7340 1717.5,7307.5 1717.5,6713.61 1850,6581.11 v1(1850,6310)
HPB_ISO24V_CURRENT: C37.2 J2.14 R28.2 | length 268.3
  Top Layer w10: J2.14@3400,400 C37.2@3400,585.39 3407.05,592.44 R28.2@3480,592.44
HPB_MEDIA_CURRENT: C56.2 J2.64 R46.2 | length 211
  Top Layer w10: R46.2@897.56,610 897.56,531.65 C56.2@899.21,530 900,529.21 J2.64@900,400
HPB_SYNCBOX_CURRENT: C55.2 J2.10 R42.2 | length 268.3
  Top Layer w10: J2.10@3600,400 C55.2@3600,585.39 3607.05,592.44 R42.2@3680,592.44
HPB_SYNCBOX_EN: J1.53 J34.1 R70D.1 R77D.1 | length 7334.8
  Top Layer w10: R70D.1@1859.53,4810 1859.53,4866.41 1850,4875.94 v1(1850,4880) 1850,4955.94 R77D.1@1845.94,4960 1845.94,5015.94 1925,5095 J34.1@2030,5095
  Int3 (Sign) w10: J1.53@1400,11600 1400,11318.89 1464.09,11254.8 1464.09,9634.8 1572.5,9526.39 1572.5,5357.5 1850,5080 v1(1850,4880)
HPB_TEMP0: C77.2 J1.44 R51.1 | length 422.7
  Bottom Layer w10: J1.44@1900,11700 1909.76,11690.24 1909.76,11654.6 1950,11614.36 1950,11512.32 1960,11502.32 R51.1@1960,11387.56 2027.05,11387.56 C77.2@2040,11374.61
HPB_TEMP1: C76.2 J1.46 R52.1 | length 439.2
  Bottom Layer w10: J1.46@1800,11700 1790.24,11690.24 1790.24,11656.43 1750,11616.19 1750,11480 1800,11430 R52.1@1800,11387.56 1802.95,11387.56 1815.91,11374.61 C76.2@1880,11374.61
HPB_TEMP2: C75.2 J1.48 R53.1 | length 422.7
  Bottom Layer w10: J1.48@1700,11700 1645.51,11645.51 1645.51,11518.75 1640,11513.23 R53.1@1640,11387.56 1642.95,11387.56 1655.91,11374.61 C75.2@1720,11374.61
HPB_TEMP3: C74.2 J1.50 R54.1 | length 449.8
  Bottom Layer w10: C74.2@1560,11374.61 1555.39,11374.61 1555.39,11378.46 1546.3,11387.56 R54.1@1480,11387.56 1480,11440 1545.51,11505.51 1545.51,11609.88 1590.24,11654.6 1590.24,11690.24 J1.50@1600,11700
HPB_TEMP4: C73.2 J1.52 R55.1 | length 452.2
  Bottom Layer w10: R55.1@1320,11387.56 1387.05,11387.56 C73.2@1400,11374.61 1400,11460 1450,11510 1450,11650 J1.52@1500,11700
HPB_VICOR1_TEMP: C80.2 J1.38 R61.1 | length 511.5
  Bottom Layer w10: J1.38@2200,11700 2245.51,11654.49 2245.51,11590.12 2405.64,11430 2430,11430 2440,11420 R61.1@2440,11387.56 2442.95,11387.56 2455.91,11374.61 C80.2@2520,11374.61
HPB_VICOR2_TEMP: C79.2 J1.40 R62.1 | length 478.2
  Bottom Layer w10: J1.40@2100,11700 2100,11690 2110,11690 2154.49,11645.51 2154.49,11565.51 2280,11440 R62.1@2280,11387.56 2282.95,11387.56 2295.91,11374.61 C79.2@2360,11374.61
HPB_VICOR3_TEMP: C78.2 J1.42 R63.1 | length 447.5
  Bottom Layer w10: J1.42@2000,11700 2045.51,11654.49 2045.51,11544.49 2120,11470 R63.1@2120,11387.56 2187.05,11387.56 C78.2@2200,11374.61
I2C_SCL: J1.26 J41.1 R67.1 U22.4 U24.3 | length 1763.8
  Top Layer w10: J1.26@2800,11700 2850,11650 2850,11480 v1(2920,11410) 2920,11087.97 3160,10847.97 3160,10690 3220,10630 3299.53,10630 R67.1@3300,10629.53 3300.47,10629.06 3339.06,10629.06 3355,10645 U24.3@3442.72,10645
  Bottom Layer w10: J41.1@2745,11370 2880,11370 v1(2920,11410) 2941.61,11388.39 U22.4@2941.61,11320.35
I2C_SDA: J1.22 J42.1 R68.1 U22.3 U24.2 | length 1833.9
  Top Layer w10: J1.22@3000,11700 3050,11650 3050,11550 2970,11470 v1(2970,11410) 2970,11262.79 3200,11032.79 3200,10720 3219.06,10700.94 R68.1@3300,10700.94 3339.06,10700.94 3345,10695 U24.2@3442.72,10695
  Bottom Layer w10: U22.3@2967.2,11320.35 2967.2,11407.2 v1(2970,11410) 2972.87,11412.87 2972.87,11437.01 2990.86,11455 3185,11455 J42.1@3265,11375
IGB1_CHA_FET_EN: J1.21
IGB1_CHA_RLY_EN: J1.17
IGB1_CHB_FET_EN: J1.29
IGB1_CHB_RLY_EN: J1.25
IGB1_CHC_FET_EN: J1.37
IGB1_CHC_RLY_EN: J1.33
IGB1_CHD_FET_EN: J1.45
IGB1_CHD_RLY_EN: J1.41
IGB2_CHA_FET_EN: J1.23
IGB2_CHA_RLY_EN: J1.19
IGB2_CHB_FET_EN: J1.31
IGB2_CHB_RLY_EN: J1.27
IGB2_CHC_FET_EN: J1.39
IGB2_CHC_RLY_EN: J1.35
IGB2_CHD_FET_EN: J1.47
IGB2_CHD_RLY_EN: J1.43
IGB_TEMP_F: J2.57
INPUT_FET_LEFT_TEMP_F: J2.63
INPUT_FET_RIGHT_TEMP_F: J2.61
IPB1_BOARD_TEMP: J1.34
IPB1_CHA_CURRENT_SET: J1.1
IPB1_CHA_I: J2.15
IPB1_CHB_CURRENT_SET: J1.5
IPB1_CHB_I: J2.23
IPB1_CHC_CURRENT_SET: J1.9
IPB1_CHC_I: J2.31
IPB1_CHD_CURRENT_SET: J1.13
IPB1_CHD_I: J2.39
IPB1_RESET: J2.36
IPB2_BOARD_TEMP: J1.36
IPB2_CHA_CURRENT_SET: J1.3
IPB2_CHA_I: J2.19
IPB2_CHB_CURRENT_SET: J1.7
IPB2_CHB_I: J2.27
IPB2_CHC_CURRENT_SET: J1.11
IPB2_CHC_I: J2.35
IPB2_CHD_CURRENT_SET: J1.15
IPB2_CHD_I: J2.43
IPB2_RESET: J2.38
ISO_5V: C67.2 C68.2 J31.1 U9.3 U16.12 U16.15 U16.16 U18.14 | length 449.8
  Top Layer w10: v1(1240,10220) 1230,10210 C67.2@1230,10170 1243.7,10156.3 1243.7,10146.3 1250,10140 U18.14@1250,10070 ; U16.12@1272.43,10377.2 1342.8,10377.2 v1(1365,10355) ; U16.15@1272.43,10453.98 U16.16@1272.43,10479.57 1306.38,10479.57 1322.16,10495.35 1340.35,10495.35 C68.2@1350,10505 ; C68.2@1350,10500.39 1354.61,10505 v1(1420,10505)
ISO_24V: C32.2 C33.2 C39.2 DC5.6 J5.1 J5.2 J29.1 L2.1 R27.2 | length 2292.4
  Top Layer w20: L2.1@2538.11,10760 2538.11,10774.61 2571.42,10807.91 2802.09,10807.91 v1(2810,10800) ; DC5.6@2800,9935 2805,9935 DC5.6@2805,9930
  Bottom Layer w20: R27.2@2557.56,10090 2557.56,10091.76 2565.28,10099.47 2593.56,10099.47 2677.91,10015.12 C33.2@2677.91,9930 DC5.6@2805,9930 2800,9925 2800,9850 2710,9760 C32.2@2710,8362.99
ISO_GND: C33.1 C36.2 C39.1 C40.1 C41.2 C42.2 C59.1 C60.1 C67.1 C68.1 DC5.5 J5.4 J5.5 J30.1 R29.1 U9.2 U16.1 U16.14 U18.9 U18.16 | length 2979.4
  Top Layer w10: v1(960,10210) C59.1@1012.44,10210 ; v1(960,10580) C60.1@1012.44,10580 ; U16.1@1007.57,10479.57 1007.57,10517.57 v1(1010,10520) ; U18.16@1150,10070 1153.36,10073.36 1153.36,10142.57 C67.1@1180.79,10170 v1(1180.79,10219.21) ; U16.14@1272.43,10428.39 1273.39,10429.34 1339.05,10429.34 v1(1340,10430.3) ; C68.1@1350,10549.61 1394.61,10549.61 v1(1420,10575) ; U18.9@1500,10070 v1(1500,10170)
  Top Layer w20: C40.1@2022.09,10650 2022.09,10567.91 2050,10540 U9.2@2050,10470 ; DC5.5@2389.69,9945.31 DC5.5@2405,9930 ; C39.1@2670,10672.09 2797.91,10672.09 v1(2800,10670) ; C42.2@2815.16,10240 v1(2890,10240) ; C41.2@2815.16,10460 v1(2900,10460)
  Bottom Layer w20: R29.1@2362.44,10090 2362.44,9981.72 2405,9939.16 DC5.5@2405,9930 ; C36.2@2490,8361.5 2490,9730 2405,9815 DC5.5@2405,9930 ; C33.1@2542.09,9930 DC5.5@2405,9930
L_24V: C2.2 C4.1 C8.2 C15.1 DC1.7 DC2.7 J23.1 Q1.3 R15.1 U5.1 | length 1235.1
  Top Layer w10: U5.1@2784.65,5195 2981.87,5195 ; Q1.3@2851.97,5739.76 2852.2,5740 2982.53,5740 2988.39,5734.14 2988.39,5311.61
  Bottom Layer w30: DC1.7@3250,2650 3253.5,2646.5 3253.5,2413.5 C2.2@3257.01,2410 ; DC2.7@3250,4600 3254.25,4595.75 3254.25,4374.25 C8.2@3258.5,4370
MVC_L_CURRENT: J2.46
MVC_L_VOLTAGE: J2.54
MVC_R_CURRENT: J2.42
MVC_R_VOLTAGE: J2.50
N187_L: C3.2 C5.1 C14.2 C16.1 DC1.4 DC2.4 J3.B J20.1 T1.1 T2.1 | length 1162.1
  Top Layer w10: C3.2@5550,3150 5550,3210 5660,3320 T1.1@5740,3320 ; C14.2@5560,5108.43 5560,5200 5680,5320 T2.1@5740,5320
  Top Layer w30: DC2.4@5250,5400 DC2.4@5271.71,5400
  Bottom Layer w10: DC1.4@5225,3450 DC1.4@5250,3450 ; DC2.4@5225,5400 DC2.4@5250,5400 ; C5.1@5250,3688.5 C5.1@5251.5,3690
  Bottom Layer w30: C16.1@5242.99,5630 5246.5,5626.5 5246.5,5403.5 DC2.4@5250,5400 ; DC1.4@5250,3450 C5.1@5250,3688.5
N187_R: C20.2 C22.1 C28.2 C30.1 DC3.4 DC4.4 J4.B J22.1 T3.1 T4.1 | length 1126
  Top Layer w10: C28.2@5526.59,9782.61 5526.59,9826.59 5680,9980 T4.1@5740,9980 ; C20.2@5590,7866.85 5590,8033.28 5590.86,8034.14 5589.14,8035.86 5589.14,8044.14 5595,8050 T3.1@5740,8050
  Top Layer w30: DC4.4@5250,10092.53 DC4.4@5250,10100 ; C20.2@5585.33,7866.85 C20.2@5590,7866.85
  Bottom Layer w30: DC3.4@5250,8150 5250.75,8150.75 5250.75,8379.25 C22.1@5251.5,8380 ; DC4.4@5250,10100 5250.75,10100.75 5250.75,10329.25 C30.1@5251.5,10330
NetC32_1: C32.1 C35.2 DC5.1 L1.4 | length 881
  Top Layer w20: 2224.29,7765.71 2224.29,7782.26 L1.4@2227.16,7785.13 ; 2290,7760 2417.91,7760 2430,7772.09 2552.09,7772.09 2705,7925 DC5.1@2705,8130
  Bottom Layer w20: DC5.1@2705,8130 2707.5,8132.5 2707.5,8297.5 C32.1@2710,8300
NetC34_2: C34.2 L1.3 R26.1 U8.5 | length 444
  Top Layer w10: U8.5@1780,7902.76 1780,7892.91 1770,7882.91 1770,7850 1819.45,7800.55 1819.45,7786.65 R26.1@1836.1,7770
  Top Layer w20: R26.1@1836.1,7770 1838.19,7772.09 C34.2@1960,7772.09 1972.09,7760 2110,7760
NetC35_1: C35.1 C36.1 DC5.2 L1.1 | length 625.1
  Top Layer w20: 2260,7920 2397.91,7920 C35.1@2410,7907.91 2412.09,7910 2470,7910 2505,7945 DC5.2@2505,8130
  Bottom Layer w20: C36.1@2490,8298.5 2497.5,8291 2497.5,8137.5 DC5.2@2505,8130
NetC40_2: C40.2 L2.2 R30.2 U9.1 | length 707.4
  Top Layer w20: U9.1@2150,10470 2157.91,10477.91 C40.2@2157.91,10650 2268.58,10650 L2.2@2301.89,10683.31 ; L2.2@2301.89,10760 L2.2@2301.89,10683.31 ; R30.2@2410,10462.05 2369.65,10462.05 2301.89,10529.8 L2.2@2301.89,10683.31
NetC41_1: C41.1 C42.1 R30.1 | length 528.8
  Top Layer w20: R30.1@2410,10217.95 2410,10300 2460,10350 2584.84,10350 ; C42.1@2562.8,10217.95 C42.1@2584.84,10240 2584.84,10350 ; C41.1@2584.84,10460 2584.84,10350
NetC44_2: C44.2 L3.2 R32.2 U10.1 | length 554.4
  Top Layer w30: L3.2@1868.11,2860 1896.06,2832.05 R32.2@2040,2832.05 ; C44.2@2040,2962.09 R32.2@2040,2832.05 ; U10.1@2280,2830 2278.98,2831.02 2041.02,2831.02 R32.2@2040,2832.05
NetC47_1: C47.1 C48.1 R32.1 | length 429.9
  Top Layer w20: 2035,2410.16 2040,2415.16
  Top Layer w30: C48.1@1910,2410.16 2035,2410.16 C47.1@2160,2410.16 ; 2040,2415.16 R32.1@2040,2587.95
NetC57_1: C57.1 U16.2 | length 132
  Top Layer w10: C57.1@880,10464.61 915.39,10464.61 926.02,10453.98 U16.2@1007.57,10453.98
NetC57_2: C57.2 U16.4 | length 132.8
  Top Layer w10: C57.2@880,10415.39 914.61,10415.39 927.2,10402.8 U16.4@1007.57,10402.8
NetC58_1: C58.1 U17.4 | length 141.1
  Top Layer w10: C58.1@870,9315.39 924.61,9315.39 957.2,9282.8 U17.4@997.57,9282.8
NetC58_2: C58.2 U17.2 | length 140.3
  Top Layer w10: C58.2@870,9364.61 925.39,9364.61 956.02,9333.98 U17.2@997.57,9333.98
NetC59_2: C59.2 U16.7 | length 168.1
  Top Layer w10: U16.7@1007.57,10326.02 1053.98,10326.02 1067.56,10312.44 C59.2@1067.56,10210
NetC60_2: C60.2 U16.3 | length 206.2
  Top Layer w10: U16.3@1007.57,10428.39 1058.39,10428.39 1067.56,10437.56 C60.2@1067.56,10580
NetC61_1: C61.1 U16.6 | length 153.1
  Top Layer w10: C61.1@880,10290 910,10290 970.38,10350.38 1006.33,10350.38 U16.6@1007.57,10351.61
NetC61_2: C61.2 U16.5 | length 140.9
  Top Layer w10: C61.2@880,10345.12 925.12,10345.12 957.2,10377.2 U16.5@1007.57,10377.2
NetC62_2: C62.2 U17.3 | length 212.8
  Top Layer w10: U17.3@997.57,9308.39 1038.39,9308.39 1087.56,9357.56 C62.2@1087.56,9460
NetC63_2: C63.2 U17.7 | length 161.5
  Top Layer w10: U17.7@997.57,9206.02 998.8,9204.79 1039.35,9204.79 1050,9194.14 C63.2@1050,9090
NetC64_1: C64.1 U17.5 | length 131.6
  Top Layer w10: C64.1@870,9247.56 917.56,9247.56 927.2,9257.2 U17.5@997.57,9257.2
NetC64_2: C64.2 U17.6 | length 143.8
  Top Layer w10: C64.2@870,9192.44 902.44,9192.44 941.61,9231.61 U17.6@997.57,9231.61
NetC88_2: C88.2 R75.1 U5.7 | length 208.5
  Top Layer w10: R75.1@2550.94,5115 2550,5115.94 2550,5145 2520,5175 C88.2@2520,5210.39 2531.81,5222.2 U5.7@2615.35,5222.2
NetC89_2: C89.2 R76.2 U7.7 | length 293.4
  Top Layer w10: U7.7@3224.65,6192.8 3265.28,6192.8 3271.14,6198.65 3271.14,6335 R76.2@3274.53,6335 ; R76.2@3274.53,6340 R76.2@3274.53,6335 ; C89.2@3355,6329.61 3341.3,6315.91 3304.35,6315.91 3294.94,6325.31 3285.28,6325.31 3285.28,6335 R76.2@3274.53,6335
NetC91A_2: C91A.2 U1A.5 | length 123.1
  Bottom Layer w10: U1A.5@3573.07,3150 3692.09,3150 C91A.2@3695,3152.91
NetC91B_2: C91B.2 U1B.5 | length 123.1
  Bottom Layer w10: U1B.5@3593.07,7860 3712.09,7860 C91B.2@3715,7862.91
NetC91C_2: C91C.2 U1C.5 | length 123.1
  Bottom Layer w10: U1C.5@3578.07,5100 3697.09,5100 C91C.2@3700,5102.91
NetC91D_2: C91D.2 U1D.5 | length 123.1
  Bottom Layer w10: U1D.5@3619.23,9966 3738.24,9966 C91D.2@3741.16,9968.91
NetC92A_2: C92A.2 U1A.6 U2A.4 | length 359.2
  Bottom Layer w10: U2A.4@3573.07,3022.4 U1A.6@3573.07,3112.6
  Bottom Layer w15: C92A.2@3512.09,2785 3512.09,2972.24 3562.24,3022.4 U2A.4@3573.07,3022.4
NetC92B_2: C92B.2 U1B.6 U2B.4 | length 359.2
  Bottom Layer w10: U2B.4@3593.07,7732.4 U1B.6@3593.07,7822.6
  Bottom Layer w15: C92B.2@3532.09,7495 3532.09,7682.24 3582.24,7732.4 U2B.4@3593.07,7732.4
NetC92C_2: C92C.2 U1C.6 U2C.4 | length 359.2
  Bottom Layer w10: U2C.4@3578.07,4972.4 U1C.6@3578.07,5062.6
  Bottom Layer w15: C92C.2@3517.09,4735 3517.09,4922.24 3567.24,4972.4 U2C.4@3578.07,4972.4
NetC92D_2: C92D.2 U1D.6 U2D.4 | length 359.2
  Bottom Layer w10: U2D.4@3619.23,9838.4 U1D.6@3619.23,9928.6
  Bottom Layer w15: C92D.2@3558.24,9601 3558.24,9788.24 3608.4,9838.4 U2D.4@3619.23,9838.4
NetD1A_1: D1A.1 Q3A.1 R69A.2 R78A.2 | length 356.2
  Top Layer w10: Q3A.1@1470.12,3469.45 1489.8,3469.45 1528.24,3507.89 1528.24,3523.4 1535.31,3530.47 R69A.2@1570,3530.47 1580.75,3541.22 1597.76,3541.22 1646.06,3589.53 R78A.2@1650,3589.53 1653.94,3589.53 1685,3620.59 D1A.1@1685,3690.2
NetD1B_1: D1B.1 Q3B.1 R69B.2 R78B.2 | length 336.5
  Top Layer w10: Q3B.1@1489.8,7129.92 1528.24,7168.36 1528.24,7183.87 1535.31,7190.94 R69B.2@1570,7190.94 1580.75,7201.69 1597.76,7201.69 1646.06,7250 R78B.2@1650,7250 1653.94,7250 1685,7281.06 D1B.1@1685,7350.67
